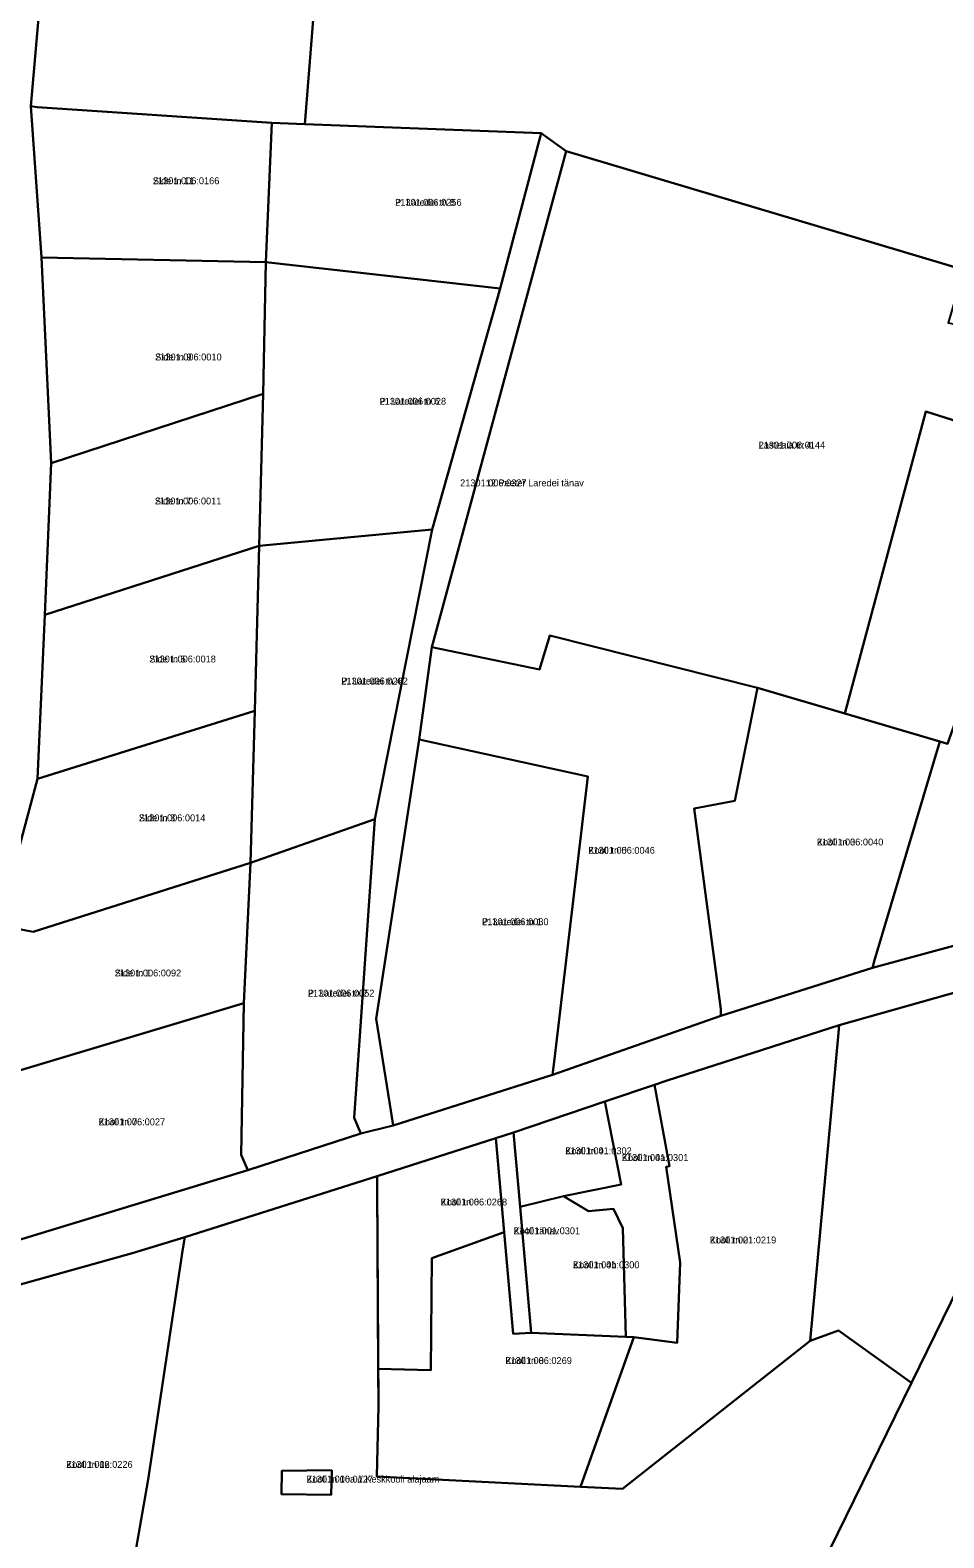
# Model space of a CAD drawing. Extents: x 520985 to 542706, y 6413723 to 6468993.
# Drawn here: x 529184.5 to 529383.8, y 6437602.7 to 6437931.4 of the extents above; entities that cross this region are included whole.
import ezdxf

# ---------------------------------------------------------------- set-up
doc = ezdxf.new("R2010")
doc.units = 0
for name, color, linetype in [('L_AADRESS', 7, 'Continuous'), ('PIIR', 7, 'Continuous'), ('TUNNUS', 7, 'Continuous')]:
    doc.layers.add(name, color=color, linetype=linetype)

msp = doc.modelspace()

# ---------------------------------------------------------------- linework, layer by layer
at = {"layer": 'PIIR'}
for points in [[(529197.65, 6438025.57), (529234.85, 6438018.17), (529237.39, 6438006.69), (529237.61, 6437996.41), (529233.67, 6437969.59), (529234.88, 6437966.86), (529246.7, 6437940.18), (529244.39, 6437910.92), (529237.23, 6437911.22), (529185.99, 6437914.68), (529184.67, 6437914.83), (529188.21, 6437955.75), (529190.59, 6437977.52), (529196.7, 6438025.81)], [(529351.31, 6437939.66), (529370, 6438022.07), (529420.28, 6438012.48), (529422.05, 6438012.14), (529422.58, 6438003.55), (529420.46, 6437993.36), (529414.69, 6437970.14), (529395.03, 6437890.95), (529393.19, 6437883.54), (529391.83, 6437878.07), (529388.15, 6437879.17), (529301.38, 6437905.02), (529295.93, 6437909), (529244.39, 6437910.92), (529246.7, 6437940.18), (529281.7, 6437955.61)], [(529184.67, 6437914.83), (529185.99, 6437914.68), (529237.23, 6437911.22), (529235.92, 6437880.88), (529186.99, 6437881.86)], [(529295.93, 6437909), (529287, 6437875.07), (529235.92, 6437880.88), (529237.23, 6437911.22), (529244.39, 6437910.92)], [(529301.38, 6437905.02), (529272.08, 6437796.93), (529269.38, 6437776.8), (529259.99, 6437715.89), (529263.13, 6437695.88), (529263.64, 6437692.6), (529256.64, 6437690.82), (529255.18, 6437694.24), (529259.66, 6437759.4), (529272.19, 6437822.54), (529287, 6437875.07), (529295.93, 6437909)], [(529388.15, 6437879.17), (529384.71, 6437867.62), (529414.74, 6437861.34), (529413.94, 6437858.8), (529407.04, 6437839.69), (529404.93, 6437840.34), (529379.87, 6437848.32), (529362.18, 6437782.43), (529343.12, 6437788), (529297.83, 6437799.46), (529295.59, 6437792.04), (529272.08, 6437796.93), (529301.38, 6437905.02)], [(529186.99, 6437881.86), (529235.92, 6437880.88), (529235.32, 6437852.12), (529189.1, 6437836.99)], [(529235.92, 6437880.88), (529287, 6437875.07), (529272.19, 6437822.54), (529234.44, 6437818.96), (529235.32, 6437852.12)], [(529446.77, 6437855.13), (529432.79, 6437808.09), (529401.62, 6437816.02), (529399.65, 6437816.53), (529386.08, 6437779.89), (529384.58, 6437775.84), (529382.9, 6437776.33), (529362.18, 6437782.43), (529379.87, 6437848.32), (529404.93, 6437840.34), (529407.04, 6437839.69), (529413.94, 6437858.8), (529414.74, 6437861.34)], [(529189.1, 6437836.99), (529235.32, 6437852.12), (529234.44, 6437818.96), (529187.7, 6437803.92)], [(529234.44, 6437818.96), (529272.19, 6437822.54), (529259.66, 6437759.4), (529232.54, 6437749.9), (529233.48, 6437783.03)], [(529187.7, 6437803.92), (529234.44, 6437818.96), (529233.48, 6437783.03), (529186.1, 6437768.16)], [(529391.8, 6437733.35), (529368.25, 6437726.95), (529368.71, 6437728.63), (529382.9, 6437776.33), (529384.58, 6437775.84), (529386.08, 6437779.89), (529399.65, 6437816.53), (529401.62, 6437816.02), (529432.79, 6437808.09), (529409.93, 6437743.09), (529413.23, 6437732.98)], [(529298.81, 6437706.49), (529306.16, 6437768.73), (529269.38, 6437776.8), (529272.08, 6437796.93), (529295.59, 6437792.04), (529297.83, 6437799.46), (529343.12, 6437788), (529338.21, 6437763.41), (529329.3, 6437761.73), (529335.12, 6437717.96), (529335.18, 6437716.53), (529298.42, 6437703.61)], [(529335.12, 6437717.96), (529329.3, 6437761.73), (529338.21, 6437763.41), (529343.12, 6437788), (529362.18, 6437782.43), (529382.9, 6437776.33), (529368.71, 6437728.63), (529368.25, 6437726.95), (529335.18, 6437716.53)], [(529186.1, 6437768.16), (529233.48, 6437783.03), (529232.54, 6437749.9), (529185.11, 6437734.82), (529177.53, 6437736.25)], [(529263.13, 6437695.88), (529259.99, 6437715.89), (529269.38, 6437776.8), (529306.16, 6437768.73), (529298.81, 6437706.49), (529298.42, 6437703.61), (529263.64, 6437692.6)], [(529230.5, 6437686.2), (529231.1, 6437719.29), (529232.54, 6437749.9), (529259.66, 6437759.4), (529255.18, 6437694.24), (529256.64, 6437690.82), (529231.94, 6437682.87)], [(529185.11, 6437734.82), (529232.54, 6437749.9), (529231.1, 6437719.29), (529167.78, 6437700.3), (529177.53, 6437736.25)], [(529419.5, 6437723.75), (529376.73, 6437636.48), (529372.86, 6437639.26), (529360.79, 6437647.88), (529354.62, 6437645.63), (529360.79, 6437712.79), (529360.94, 6437714.44), (529393.68, 6437723.74), (529401.48, 6437724.11), (529412.24, 6437723.24)], [(529175.79, 6437668.97), (529169.4, 6437674.03), (529167.78, 6437700.3), (529231.1, 6437719.29), (529230.5, 6437686.2), (529231.94, 6437682.87), (529176.58, 6437665.99)], [(529323.92, 6437683.76), (529320.68, 6437701.47), (529323.43, 6437702.38), (529360.94, 6437714.44), (529360.79, 6437712.79), (529354.62, 6437645.63), (529313.67, 6437613.35), (529304.54, 6437613.79), (529316.21, 6437646.43), (529325.64, 6437645.22), (529326.31, 6437662.73), (529323.24, 6437683.6)], [(529313.39, 6437679.76), (529309.82, 6437697.8), (529320.68, 6437701.47), (529323.92, 6437683.76), (529323.24, 6437683.6), (529326.31, 6437662.73), (529325.64, 6437645.22), (529316.21, 6437646.43), (529314.4, 6437646.48), (529313.77, 6437670.21), (529311.73, 6437674.45), (529306.31, 6437673.89), (529300.81, 6437677.21)], [(529291.4, 6437674.85), (529289.9, 6437691.09), (529309.82, 6437697.8), (529313.39, 6437679.76), (529300.81, 6437677.21)], [(529286.09, 6437689.84), (529287.91, 6437669.37), (529272.11, 6437663.64), (529271.92, 6437639.23), (529266.12, 6437639.39), (529260.42, 6437639.56), (529260.18, 6437679.13), (529260.16, 6437681.53)], [(529293.81, 6437647.41), (529289.86, 6437647.2), (529287.91, 6437669.37), (529286.09, 6437689.84), (529289.9, 6437691.09), (529291.4, 6437674.85)], [(529293.81, 6437647.41), (529291.4, 6437674.85), (529300.81, 6437677.21), (529306.31, 6437673.89), (529311.73, 6437674.45), (529313.77, 6437670.21), (529314.4, 6437646.48)], [(529272.11, 6437663.64), (529287.91, 6437669.37), (529289.86, 6437647.2), (529293.81, 6437647.41), (529314.4, 6437646.48), (529316.21, 6437646.43), (529304.54, 6437613.79), (529260.11, 6437616.08), (529260.47, 6437631.4), (529260.42, 6437639.56), (529266.12, 6437639.39), (529271.92, 6437639.23)], [(529181.26, 6437657.64), (529207.04, 6437664.8), (529218.21, 6437668.23), (529217.82, 6437665.67), (529210.2, 6437615.42), (529202.94, 6437573.84), (529166.48, 6437578.36), (529180.71, 6437654.67)], [(529250.28, 6437617.43), (529250.16, 6437612.05), (529239.28, 6437612.21), (529239.36, 6437617.29)], [(529250.28, 6437617.43), (529239.36, 6437617.29), (529239.28, 6437612.21), (529250.16, 6437612.05)]]:
    msp.add_lwpolyline(points, close=True, dxfattribs=at)
for points in [[(529171.7, 6437219.39), (529245.83, 6437371.03), (529273.22, 6437425.26), (529376.73, 6437636.48), (529419.5, 6437723.75), (529424.61, 6437735.19), (529429.18, 6437733.16), (529461.26, 6437798.64), (529483.33, 6437847.76), (529486.73, 6437855.22), (529521.09, 6437929.51), (529534.42, 6437964.27)], [(529188.21, 6437955.75), (529184.67, 6437914.83), (529186.99, 6437881.86), (529189.1, 6437836.99), (529187.7, 6437803.92), (529186.1, 6437768.16), (529177.53, 6437736.25), (529167.78, 6437700.3), (529169.4, 6437674.03), (529175.79, 6437668.97), (529176.58, 6437665.99), (529162.25, 6437663.31), (529161.69, 6437703.93), (529169.63, 6437737.7), (529179.82, 6437768.52), (529182.25, 6437836.61), (529181.97, 6437843.59), (529180.72, 6437881.04), (529180.31, 6437915.23), (529180.57, 6437934.75)], [(529176.58, 6437665.99), (529231.94, 6437682.87), (529256.64, 6437690.82), (529263.64, 6437692.6), (529298.42, 6437703.61), (529335.18, 6437716.53), (529368.25, 6437726.95), (529391.8, 6437733.35), (529413.23, 6437732.98), (529424.61, 6437735.19), (529419.5, 6437723.75), (529412.24, 6437723.24), (529401.48, 6437724.11), (529393.68, 6437723.74), (529360.94, 6437714.44), (529323.43, 6437702.38), (529320.68, 6437701.47), (529309.82, 6437697.8), (529289.9, 6437691.09), (529286.09, 6437689.84), (529260.16, 6437681.53), (529218.21, 6437668.23), (529207.04, 6437664.8), (529181.26, 6437657.64)], [(529166.48, 6437578.36), (529202.94, 6437573.84), (529210.2, 6437615.42), (529217.82, 6437665.67), (529218.21, 6437668.23), (529260.16, 6437681.53), (529260.18, 6437679.13), (529260.47, 6437631.4), (529260.11, 6437616.08), (529304.54, 6437613.79), (529313.67, 6437613.35), (529354.62, 6437645.63), (529360.79, 6437647.88), (529372.86, 6437639.26), (529376.73, 6437636.48), (529273.22, 6437425.26), (529175.58, 6437446.49)]]:
    msp.add_lwpolyline(points, dxfattribs=at)

# ---------------------------------------------------------------- texts
at = {"layer": 'L_AADRESS'}
for s, p in [('Side tn 11', (529211.26, 6437897.85)), ('P. Laredei tn 8', (529264.1, 6437893.15)), ('Side tn 9', (529211.76, 6437859.42)), ('P. Laredei tn 6', (529260.72, 6437849.76)), ('Lasteaia tn 4', (529343.41, 6437840.21)), ('2130112 Peeter Laredei tänav', (529278.28, 6437831.97)), ('Side tn 7', (529211.7, 6437828.02)), ('Side tn 5', (529210.5, 6437793.56)), ('P. Laredei tn 4', (529252.36, 6437788.75)), ('Side tn 3', (529208.21, 6437758.93)), ('Kooli tn 3', (529356.1, 6437753.66)), ('Kooli tn 5', (529306.25, 6437751.85)), ('P. Laredei tn 1', (529283.07, 6437736.27)), ('Side tn 1', (529202.94, 6437725.1)), ('P. Laredei tn 2', (529245.08, 6437720.7)), ('Kooli tn 7', (529199.43, 6437692.64)), ('Kooli tn 4', (529301.22, 6437686.33)), ('Kooli tn 4a', (529313.56, 6437684.86)), ('Kooli tn 6', (529274.03, 6437675.16)), ('Kooli tänav', (529289.95, 6437668.88)), ('Kooli tn 2', (529332.74, 6437666.88)), ('Kooli tn 4b', (529302.9, 6437661.47)), ('Kooli tn 8', (529288.16, 6437640.58)), ('Kooli tn 12', (529192.34, 6437617.94)), ('Kooli tn 10a // Keskkooli alajaam', (529244.77, 6437614.74))]:
    msp.add_text(s, height=1.5, dxfattribs=at).set_placement(p)
at = {"layer": 'TUNNUS'}
for s, p in [('21301:006:0166', (529211.26, 6437897.85)), ('21301:006:0256', (529264.1, 6437893.15)), ('21301:006:0010', (529211.76, 6437859.42)), ('21301:006:0028', (529260.72, 6437849.76)), ('21301:006:0144', (529343.41, 6437840.21)), ('21301:006:0327', (529278.28, 6437831.97)), ('21301:006:0011', (529211.7, 6437828.02)), ('21301:006:0018', (529210.5, 6437793.56)), ('21301:006:0262', (529252.36, 6437788.75)), ('21301:006:0014', (529208.21, 6437758.93)), ('21301:006:0040', (529356.1, 6437753.66)), ('21301:006:0046', (529306.25, 6437751.85)), ('21301:006:0030', (529283.07, 6437736.27)), ('21301:006:0092', (529202.94, 6437725.1)), ('21301:006:0052', (529245.08, 6437720.7)), ('21301:006:0027', (529199.43, 6437692.64)), ('21301:001:0302', (529301.22, 6437686.33)), ('21301:001:0301', (529313.56, 6437684.86)), ('21301:006:0268', (529274.03, 6437675.16)), ('21401:001:0301', (529289.95, 6437668.88)), ('21301:001:0219', (529332.74, 6437666.88)), ('21301:001:0300', (529302.9, 6437661.47)), ('21301:006:0269', (529288.16, 6437640.58)), ('21301:006:0226', (529192.34, 6437617.94)), ('21301:006:0127', (529244.77, 6437614.74))]:
    msp.add_text(s, height=1.5, dxfattribs=at).set_placement(p)

doc.saveas('drawing.dxf')
